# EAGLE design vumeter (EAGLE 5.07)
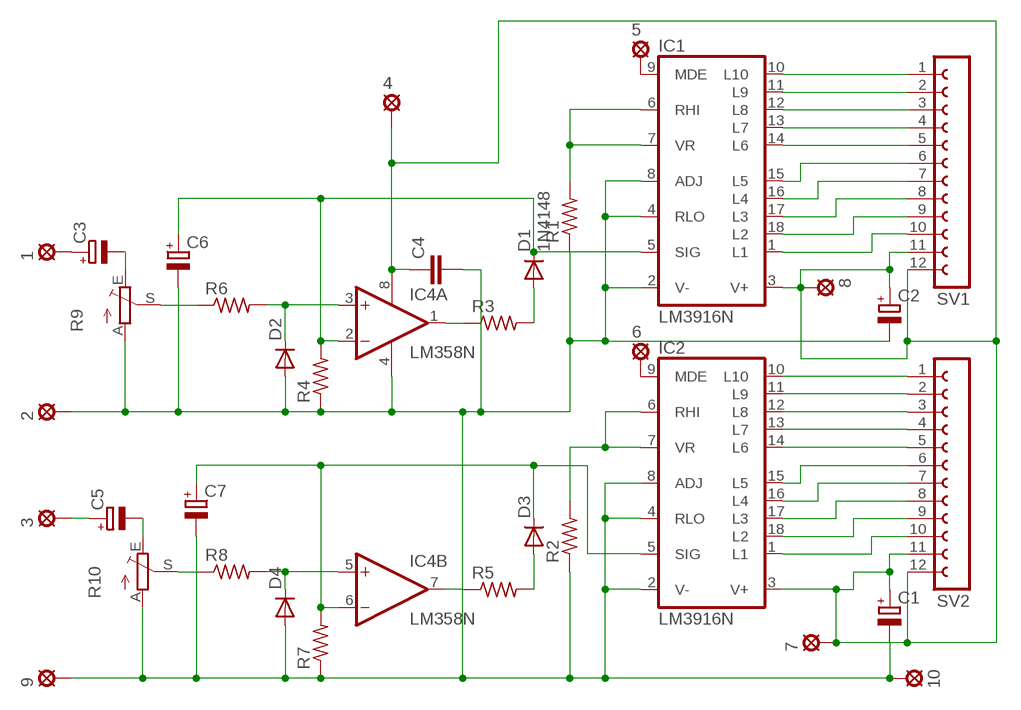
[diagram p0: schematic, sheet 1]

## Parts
1  SE11  [SE11]
2  SE11  [SE11]
3  SE11  [SE11]
4  SE11  [SE11]
5  SE11  [SE11]
6  SE11  [SE11]
7  SE11  [SE11]
8  SE11  [SE11]
9  SE11  [SE11]
10  SE11  [SE11]
C1  CPOL-EUE2.5-5  [E2,5-5]
C2  CPOL-EUE2.5-5  [E2,5-5]
C3  CPOL-EUE2.5-5  [E2,5-5]
C4  C-EU050-025X075  [C050-025X075]
C5  CPOL-EUE2.5-5  [E2,5-5]
C6  CPOL-EUE2.5-5  [E2,5-5]
C7  CPOL-EUE2.5-5  [E2,5-5]
D1  1N4148  1N4004  [DO41-10]
D2  1N4004  [DO41-10]
D3  1N4004  [DO41-10]
D4  1N4004  [DO41-10]
IC1  LM3916N  LM3914N  [DIL18]
IC2  LM3916N  LM3914N  [DIL18]
IC4  LM358N  [DIL08]
R1  R-US_0207/10  [0207/10]
R2  R-US_0207/10  [0207/10]
R3  R-US_0207/10  [0207/10]
R4  R-US_0207/10  [0207/10]
R5  R-US_0207/10  [0207/10]
R6  R-US_0207/10  [0207/10]
R7  R-US_0207/10  [0207/10]
R8  R-US_0207/10  [0207/10]
R9  TRIM_EU-LI10  [LI10]
R10  TRIM_EU-LI10  [LI10]
SV1  FE12-1  [FE12]
SV2  FE12-1  [FE12]

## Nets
N$1: 5.MP IC1.9(MDE)
N$2: IC1.6(RHI) IC1.7(VR) R1.2
N$3: 1.MP C3.+
N$4: IC1.10(L10) SV1.1
N$5: IC1.11(L9) SV1.2
N$6: IC1.12(L8) SV1.3
N$7: IC1.13(L7) SV1.4
N$8: IC1.14(L6) SV1.5
N$9: IC1.15(L5) SV1.6
N$10: IC1.16(L4) SV1.7
N$11: IC1.17(L3) SV1.8
N$12: IC1.18(L2) SV1.9
N$13: IC2.10(L10) SV2.1
N$14: IC1.1(L1) SV1.10
N$15: IC2.11(L9) SV2.2
N$16: IC2.12(L8) SV2.3
N$17: IC2.13(L7) SV2.4
N$18: IC2.14(L6) SV2.5
N$19: IC2.15(L5) SV2.6
N$20: IC2.16(L4) SV2.7
N$21: IC2.17(L3) SV2.8
N$22: IC2.18(L2) SV2.9
N$23: IC2.1(L1) SV2.10
N$24: IC2.6(RHI) IC2.7(VR) R2.2
N$26: 2.MP 9.MP 10.MP C1.- C2.- C4.2 C6.- C7.- D2.A D4.A IC1.2(V-) IC1.4(RLO) IC1.8(ADJ) IC2.2(V-) IC2.4(RLO) IC2.8(ADJ) IC4.4(P:V-) R1.1 R2.1 R4.1 R7.1 R9.A R10.A
N$28: 4.MP 7.MP 8.MP C1.+ C2.+ C4.1 IC1.3(V+) IC2.3(V+) IC4.8(P:V+) SV1.11 SV1.12 SV2.11 SV2.12
N$29: 6.MP IC2.9(MDE)
N$30: IC4.1(A:OUT) R3.1
N$31: D1.A R3.2
N$32: 3.MP C5.+
N$33: R6.1 R9.S
N$34: C6.+ D1.C IC1.5(SIG) IC4.2(A:-IN) R4.2
N$35: C3.- R9.E
N$36: D2.C IC4.3(A:+IN) R6.2
N$38: IC4.7(B:OUT) R5.1
N$39: D3.A R5.2
N$40: C7.+ D3.C IC2.5(SIG) IC4.6(B:-IN) R7.2
N$42: D4.C IC4.5(B:+IN) R8.2
N$43: R8.1 R10.S
N$44: C5.- R10.E

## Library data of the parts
1-10 = solpad:SE11: SOLDER PAD
C1-C3 C5-C7 = resistor:CPOL-EU: POLARIZED CAPACITOR, European symbol
C4 = resistor:C-EU: CAPACITOR, European symbol
D1-D4 = diode:1N4004: DIODE
IC1 IC2 = linear:LM3914N: LED DRIVER senses analog voltage levels and drives 10 LEDs
IC4 = linear:LM358: OP AMP also LM158; LM258; LM2904 Source: http://cache.national.com/ds/LM/LM158.pdf
R1-R8 = resistor:R-US_: RESISTOR, American symbol
R9 R10 = pot:TRIM_EU-: POTENTIOMETER
SV1 SV2 = con-lsta:FE12-1: FEMALE HEADER

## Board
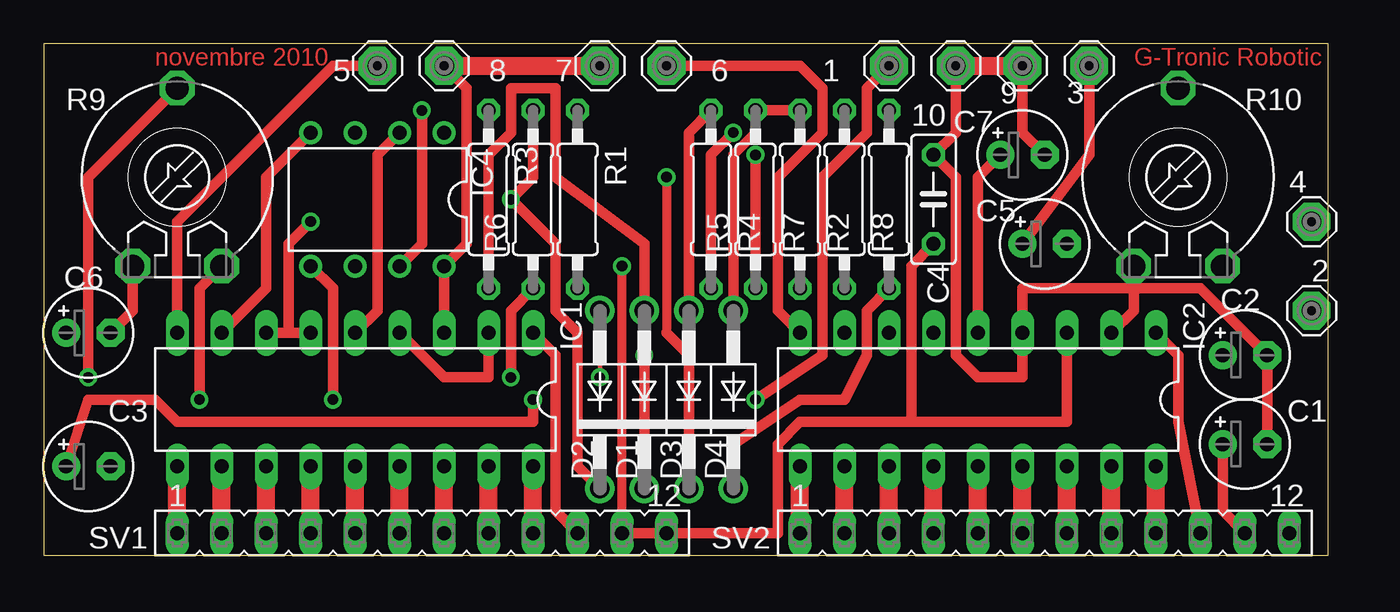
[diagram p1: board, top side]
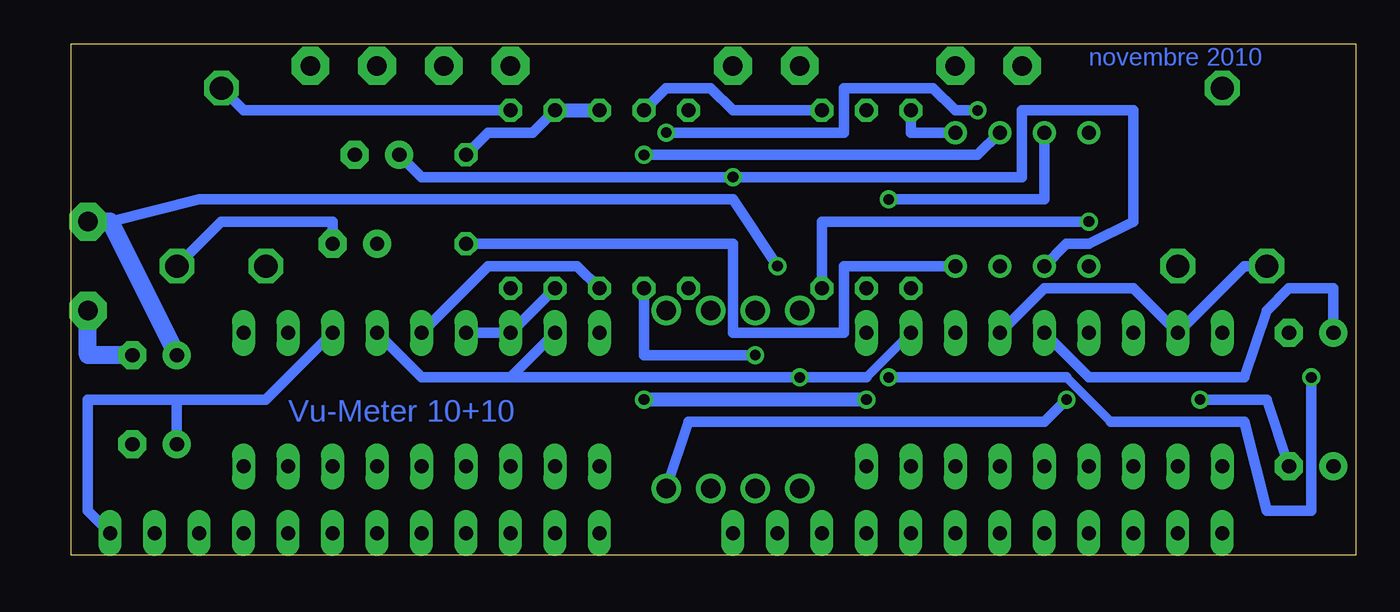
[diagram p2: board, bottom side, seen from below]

Size 73.33 x 29.2 mm. Coordinates in mm from the lower left corner, seen from the top.
Outline: 0,0 73.33,0 73.33,29.2 0,29.2 0,0
Copper layers (1*16): Top 0.035mm / dielectric 1.5mm / Bottom 0.035mm
Design rules "default": minimum track width 10mil, minimum drill 24mil, track to track 8mil, track to pad 8mil, pad to pad 8mil, via to via 8mil, smd to smd 8mil, copper to edge 40mil, drill to drill 8mil, minimum pad ring 10mil, minimum via ring 8mil, stop-mask expansion 4mil, vias tented up to drill 0mil, thermal gap 10mil

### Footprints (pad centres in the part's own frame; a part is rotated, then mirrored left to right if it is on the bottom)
SE11 = drill 1.118 pad 2.159 octagon: MP 0,0
E2,5-5 = drill 0.813 pad 1.6 round: + -1.27,0 | drill 0.813 pad 1.6 octagon: - 1.27,0
C050-025X075 = drill 0.813 octagon: 1 -2.54,0; 2 2.54,0
DO41-10 = drill 1.118 round: A 5.08,0; C -5.08,0
DIL18 = drill 0.813 long: 1 -10.16,-3.81; 2 -7.62,-3.81; 3 -5.08,-3.81; 4 -2.54,-3.81; 5 0,-3.81; 6 2.54,-3.81; 7 5.08,-3.81; 8 7.62,-3.81; 9 10.16,-3.81; 10 10.16,3.81; 11 7.62,3.81; 12 5.08,3.81; 13 2.54,3.81; 14 0,3.81; 15 -2.54,3.81; 16 -5.08,3.81; 17 -7.62,3.81; 18 -10.16,3.81
DIL08 = drill 0.813 pad 1.27 round: 1 -3.81,-3.81; 2 -1.27,-3.81; 3 1.27,-3.81; 4 3.81,-3.81; 5 3.81,3.81; 6 1.27,3.81; 7 -1.27,3.81; 8 -3.81,3.81
0207/10 = drill 0.813 octagon: 1 -5.08,0; 2 5.08,0
LI10 = drill 1.321 octagon: A -2.54,-5.08; E 2.54,-5.08; S 0,5.08
FE12 = drill 0.813 long: 1 -13.97,0; 2 -11.43,0; 3 -8.89,0; 4 -6.35,0; 5 -3.81,0; 6 -1.27,0; 7 1.27,0; 8 3.81,0; 9 6.35,0; 10 8.89,0; 11 11.43,0; 12 13.97,0

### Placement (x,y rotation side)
1  48.26,27.94 0 top
2  72.39,13.97 0 top
3  59.69,27.94 0 top
4  72.39,19.05 0 top
5  19.05,27.94 0 top
6  35.56,27.94 0 top
7  31.75,27.94 0 top
8  22.86,27.94 0 top
9  55.88,27.94 0 top
10  52.07,27.94 0 top
C1  68.58,6.35 0 top
C2  68.58,11.43 0 top
C3  2.54,5.08 0 top
C4  50.8,20.32 90 top
C5  57.15,17.78 0 top
C6  2.54,12.7 0 top
C7  55.88,22.86 0 top
D1  34.29,8.89 90 top
D2  31.75,8.89 90 top
D3  36.83,8.89 90 top
D4  39.37,8.89 90 top
IC1  17.78,8.89 180 top
IC2  53.34,8.89 180 top
IC4  19.05,20.32 180 top
R1  30.48,20.32 270 top
R2  45.72,20.32 270 top
R3  25.4,20.32 270 top
R4  40.64,20.32 270 top
R5  38.1,20.32 90 top
R6  27.94,20.32 90 top
R7  43.18,20.32 270 top
R8  48.26,20.32 270 top
R9  7.62,21.59 0 top
R10  64.77,21.59 0 top
SV1  21.59,1.27 0 top
SV2  57.15,1.27 0 top

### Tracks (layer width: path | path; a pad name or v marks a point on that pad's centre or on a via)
N$1
  Top 0.61: IC1.9 7.62,19.05 16.51,27.94 5.MP
N$2  (via drill 0.61)
  Top 0.61: 13.97,12.7 IC1.6 | IC1.7 13.97,12.7 | v15.24,19.05 13.97,17.78 13.97,12.7
  Bottom 0.61: R1.2 30.48,19.05 v15.24,19.05
N$3  (via drill 0.61)
  Top 0.61: C3.+ 2.54,8.89 6.35,8.89 7.62,7.62 27.94,7.62 v27.94,8.89 | v40.64,8.89 44.45,11.43 44.45,21.59 46.99,24.13 46.99,26.67 1.MP
  Bottom 0.813: v27.94,8.89 v40.64,8.89
N$4
  Top 1.016: SV1.1 IC1.10
N$5
  Top 1.016: SV1.2 IC1.11
N$6
  Top 1.016: SV1.3 IC1.12
N$7
  Top 1.016: SV1.4 IC1.13
N$8
  Top 1.016: SV1.5 IC1.14
N$9
  Top 1.016: SV1.6 IC1.15
N$10
  Top 1.016: SV1.7 IC1.16
N$11
  Top 1.016: SV1.8 IC1.17
N$12
  Top 1.016: SV1.9 IC1.18
N$13
  Top 1.016: SV2.1 IC2.10
N$14
  Top 0.61: SV1.10 29.21,2.54 29.21,11.43 IC1.1
N$15
  Top 1.016: SV2.2 IC2.11
N$16
  Top 1.016: SV2.3 IC2.12
N$17
  Top 1.016: SV2.4 IC2.13
N$18
  Top 1.016: SV2.5 IC2.14
N$19
  Top 1.016: SV2.6 IC2.15
N$20
  Top 1.016: SV2.7 IC2.16
N$21
  Top 1.016: SV2.8 IC2.17
N$22
  Top 1.016: SV2.9 IC2.18
N$23
  Top 0.61: SV2.10 64.77,7.62 64.77,11.43 IC2.1
N$24
  Bottom 0.61: IC2.6 IC2.7 R2.2
N$26  (via drill 0.61)
  Top 0.254: v31.75,10.16 D2.A
  Top 0.559: 40.64,24.13 39.37,22.86
  Top 0.61: 10.MP 52.07,24.13 C4.2 52.07,21.59 52.07,11.43 53.34,10.16 55.88,10.16 IC2.4 55.88,15.24 62.23,15.24 | C7.- 55.88,24.13 9.MP | R7.1 R4.1 40.64,24.13 | 39.37,22.86 D4.A | C1.- C2.- 66.04,15.24 62.23,15.24 | IC2.2 62.23,13.97 62.23,15.24 | C6.- 5.08,13.97 R9.A | IC1.4 22.86,10.16 25.4,10.16 IC1.2 | 62.23,15.24 R10.A | IC4.4 12.7,21.59 12.7,15.24 IC1.8
  Top 1.016: 10.MP 9.MP
  Bottom 0.508: IC1.2 27.94,10.16
  Bottom 0.61: R1.1 35.56,25.4 36.83,26.67 39.37,26.67 R4.1 | C4.2 49.53,24.13 46.99,24.13 R2.1 | R9.A 6.35,16.51 IC1.8 12.7,15.24 17.78,15.24 IC1.4 | 48.26,10.16 IC2.8 | 48.26,10.16 53.34,10.16 IC2.4 | 27.94,10.16 v31.75,10.16 48.26,10.16
  Bottom 0.813: R2.1 R7.1
  Bottom 1.016: 2.MP 72.39,11.43 C2.-
N$28  (via drill 0.61)
  Top 0.508: SV1.11 v33.02,16.51
  Top 0.61: IC1.3 IC4.8 24.13,17.78 24.13,26.67 8.MP | 49.53,7.62 58.42,7.62 IC2.3 | 49.53,7.62 43.18,7.62 41.91,6.35 41.91,1.27 SV1.12 SV1.11 | C4.1 49.53,16.51 49.53,7.62 | SV2.11 67.31,2.54 C1.+
  Top 1.016: 8.MP 7.MP
  Bottom 0.61: SV2.12 72.39,2.54 72.39,8.89 67.31,8.89 | 67.31,8.89 62.23,8.89 IC2.3 | IC4.8 29.21,16.51 29.21,12.7 35.56,12.7 35.56,17.78 C4.1 | v33.02,16.51 35.56,20.32 66.04,20.32 71.12,19.05 | 67.31,8.89 C1.+
  Bottom 1.016: C2.+ 71.12,19.05 4.MP
N$29
  Top 0.61: IC2.9 41.91,13.97 41.91,21.59 44.45,24.13 44.45,26.67 43.18,27.94 6.MP
N$30
  Bottom 0.61: IC4.1 25.4,24.13 R3.1
N$31
  Top 0.61: R3.2 25.4,22.86 26.67,24.13 26.67,26.67 29.21,26.67 29.21,21.59 34.29,17.78 D1.A
N$32
  Top 0.61: C5.+ 59.69,22.86 3.MP
N$33  (via drill 0.61)
  Top 0.61: R6.1 26.67,13.97 v26.67,10.16 | v2.54,10.16 2.54,21.59 R9.S
  Bottom 0.508: 13.97,7.62 16.51,10.16
  Bottom 0.61: 16.51,10.16 v26.67,10.16 | 13.97,7.62 6.35,7.62 5.08,2.54 2.54,2.54 v2.54,10.16
N$34  (via drill 0.61)
  Top 0.61: v34.29,11.43 D1.C | IC1.5 19.05,13.97 19.05,22.86 IC4.2 | v40.64,22.86 R4.2
  Bottom 0.61: R4.2 40.64,11.43 v34.29,11.43 | C6.+ 1.27,15.24 3.81,15.24 5.08,13.97 6.35,10.16 15.24,10.16 IC1.5 | v40.64,22.86 21.59,22.86 IC4.2
N$35  (via drill 0.61)
  Top 0.61: v8.89,8.89 8.89,15.24 R9.E
  Bottom 0.61: C3.- 5.08,8.89 v8.89,8.89
N$36  (via drill 0.61)
  Top 0.61: R6.2 27.94,21.59 v26.67,20.32 29.21,17.78 29.21,13.97 30.48,12.7 30.48,5.08 D2.C
  Bottom 0.61: IC4.3 17.78,20.32 v26.67,20.32
N$38  (via drill 0.61)
  Top 0.61: IC4.7 21.59,17.78 v21.59,25.4 | v39.37,24.13 38.1,22.86 R5.1
  Bottom 0.61: v21.59,25.4 22.86,25.4 24.13,26.67 29.21,26.67 29.21,24.13 v39.37,24.13
N$39
  Top 0.61: R5.2 36.83,24.13 D3.A
N$40  (via drill 0.61)
  Top 0.508: v35.56,21.59 35.56,12.7
  Top 0.61: IC2.5 53.34,21.59 C7.+ | D3.C 36.83,11.43 35.56,12.7
  Bottom 0.61: IC4.6 16.51,17.78 15.24,17.78 12.7,19.05 12.7,25.4 19.05,25.4 19.05,21.59 v35.56,21.59 53.34,21.59 C7.+ | R7.2 44.45,16.51 49.53,16.51 IC2.5
N$42  (via drill 0.61)
  Top 0.61: IC4.5 16.51,15.24 v16.51,8.89 | R8.2 46.99,13.97 46.99,11.43 45.72,8.89 43.18,8.89 39.37,6.35 D4.C
  Bottom 0.61: v16.51,8.89 17.78,7.62 38.1,7.62 D4.C
N$43
  Bottom 0.61: R8.1 63.5,25.4 R10.S
N$44
  Bottom 0.61: C5.- 58.42,19.05 64.77,19.05 R10.E

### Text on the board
Top: novembre 2010 | G-Tronic Robotic
Bottom: novembre 2010 | Vu-Meter 10+10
